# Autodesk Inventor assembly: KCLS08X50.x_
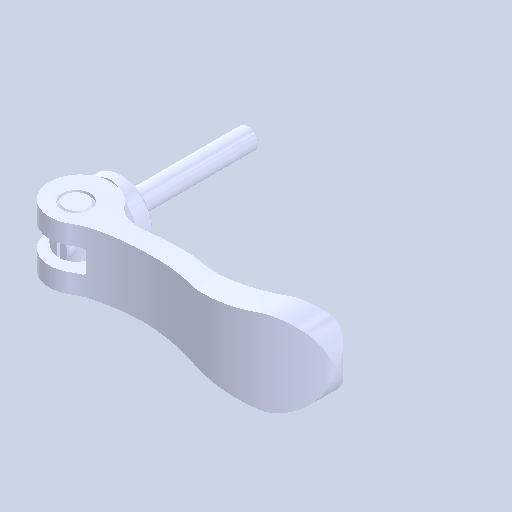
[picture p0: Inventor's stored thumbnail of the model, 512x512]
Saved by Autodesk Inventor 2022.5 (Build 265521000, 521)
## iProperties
Created: 2024-08
Part Number: KCLS08X50.x_
Document SubType Name: Assembly
Designer: ImaoCorp
Author: ImaoCorp
Sending System: SOLIDWORKS 2022-2022290
MC: AMD64
MC_MODEL: Intel64 Family 6 Model 60 Stepping 3, GenuineIntel
OS: Windows_NT
FRU: Parasolid Version 33.1, build 260,  4-25-2022
FORMAT: text
GUISE: transmit
KEY: FILEKCLS08X50.x_t
DATE: Thu Aug 29 10:55:13 2024
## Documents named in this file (5)
- Y:\5.更新分\2024年対応\1001_KCL\データ\kcls08x50\KCLS08X50.x_.iam
- Y:\5.更新分\2024年対応\1001_KCL\データ\kcls08x50\KCLS08X50_01.ipt
- Y:\5.更新分\2024年対応\1001_KCL\データ\kcls08x50\KCLS08X50_02.ipt
- Y:\5.更新分\2024年対応\1001_KCL\データ\kcls08x50\KCLS08X50_03.ipt
- Y:\5.更新分\2024年対応\1001_KCL\データ\kcls08x50\KCLS08X50_04.ipt
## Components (4 placed, 4 different names)
1. KCLS08X50_01
2. KCLS08X50_02
3. KCLS08X50_03
4. KCLS08X50_04
